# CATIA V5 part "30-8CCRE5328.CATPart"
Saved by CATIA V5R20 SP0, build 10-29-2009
Part number: 30-8CCRE5328
Revision: ANY
Definition: UNKNOWN
Nomenclature: 30-8CCRE5328
Source: Unknown
Bounding box of the stored display mesh (mm): x 0 to 50, y 0 to 6.7, z -30 to 0
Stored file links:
  C:\Users\Utente\Desktop\IO LAVORO\3D X SITO CF\CUMSA\3D files CC\CCHS5328\30-8CCRE5328.CATPart
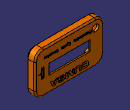
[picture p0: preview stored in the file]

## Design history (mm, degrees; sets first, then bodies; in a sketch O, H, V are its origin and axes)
Body1 "Saliente-Extruir8[1]" (main body)
  Solid1: solid without history
Body2 "Saliente-Extruir8[2]"
  Solid2: solid without history
Body3 "Saliente-Extruir8[3]"
  Solid3: solid without history
Body4 "Redondeo1"
  Solid4: solid without history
